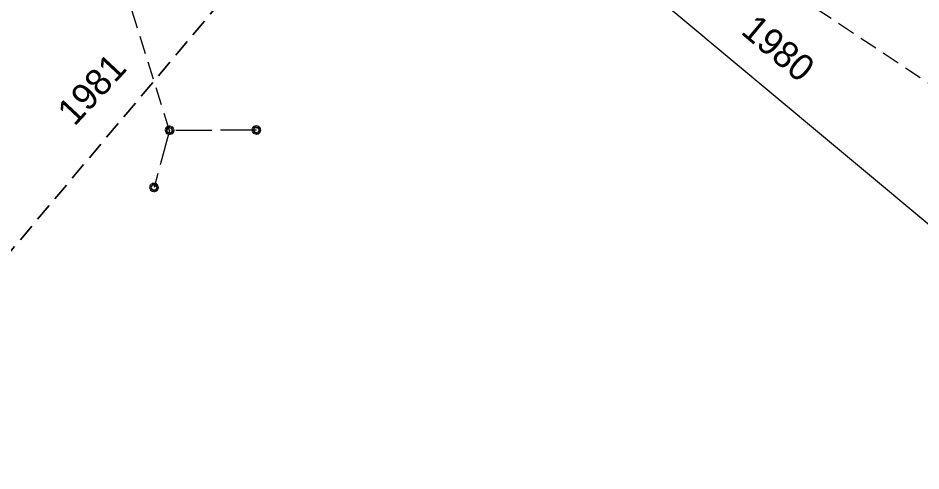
# Model space of a CAD drawing. Extents: x -742876 to -742577, y -1054710 to -1054452.
# Drawn here: x -742762.7 to -742708.1, y -1054549.5 to -1054522.1 of the extents above; entities that cross this region are included whole.
import ezdxf

# ---------------------------------------------------------------- set-up
doc = ezdxf.new("R2010")
doc.units = 0
doc.header["$LTSCALE"] = 0.36
doc.linetypes.add('LONG_DASHED', pattern=[7.5, 6, -1.5])
doc.linetypes.add('MEDIUM_DASHED', pattern=[4.5, 3, -1.5])
for name, color, linetype, lineweight in [('1', 7, 'MEDIUM_DASHED', 25), ('4', 7, 'Continuous', 13), ('8', 7, 'Continuous', 13)]:
    doc.layers.add(name, color=color, linetype=linetype, lineweight=lineweight)

msp = doc.modelspace()

# ---------------------------------------------------------------- linework, layer by layer
at = {"layer": '4', "linetype": 'MEDIUM_DASHED', "lineweight": 25}
msp.add_lwpolyline([(-742753.489, -1054528.94), (-742756.25, -1054520.12), (-742754.84, -1054517.31), (-742755.66, -1054516.33), (-742766.1, -1054507.8), (-742772.293, -1054515.246), (-742785.96, -1054502.911)], dxfattribs=at)
at = {"layer": '4'}
for points in [[(-742753.225, -1054528.927), (-742753.23, -1054528.871), (-742753.247, -1054528.818), (-742753.276, -1054528.769), (-742753.315, -1054528.728), (-742753.36, -1054528.696), (-742753.413, -1054528.674), (-742753.468, -1054528.663), (-742753.524, -1054528.665), (-742753.578, -1054528.678), (-742753.629, -1054528.703), (-742753.674, -1054528.738), (-742753.71, -1054528.781), (-742753.735, -1054528.831), (-742753.75, -1054528.886), (-742753.752, -1054528.942), (-742753.744, -1054528.997), (-742753.723, -1054529.05), (-742753.691, -1054529.096), (-742753.651, -1054529.135), (-742753.603, -1054529.165), (-742753.551, -1054529.184), (-742753.495, -1054529.191), (-742753.438, -1054529.187), (-742753.384, -1054529.17), (-742753.335, -1054529.143), (-742753.294, -1054529.105), (-742753.261, -1054529.06), (-742753.237, -1054529.009), (-742753.225, -1054528.954)], [(-742753.284, -1054528.93), (-742753.289, -1054528.881), (-742753.308, -1054528.835), (-742753.335, -1054528.794), (-742753.372, -1054528.761), (-742753.416, -1054528.739), (-742753.465, -1054528.727), (-742753.514, -1054528.727), (-742753.561, -1054528.739), (-742753.605, -1054528.762), (-742753.642, -1054528.795), (-742753.671, -1054528.836), (-742753.688, -1054528.883), (-742753.693, -1054528.932), (-742753.686, -1054528.981), (-742753.669, -1054529.027), (-742753.641, -1054529.067), (-742753.603, -1054529.1), (-742753.559, -1054529.122), (-742753.511, -1054529.134), (-742753.462, -1054529.133), (-742753.414, -1054529.121), (-742753.37, -1054529.097), (-742753.333, -1054529.064), (-742753.306, -1054529.023), (-742753.289, -1054528.976)], [(-742747.981, -1054528.913), (-742747.987, -1054528.857), (-742748.004, -1054528.804), (-742748.032, -1054528.755), (-742748.071, -1054528.714), (-742748.117, -1054528.682), (-742748.169, -1054528.66), (-742748.224, -1054528.649), (-742748.28, -1054528.651), (-742748.335, -1054528.664), (-742748.386, -1054528.689), (-742748.43, -1054528.724), (-742748.466, -1054528.767), (-742748.491, -1054528.817), (-742748.506, -1054528.872), (-742748.509, -1054528.928), (-742748.5, -1054528.983), (-742748.479, -1054529.036), (-742748.448, -1054529.082), (-742748.407, -1054529.121), (-742748.36, -1054529.151), (-742748.307, -1054529.17), (-742748.251, -1054529.177), (-742748.195, -1054529.173), (-742748.141, -1054529.156), (-742748.092, -1054529.129), (-742748.05, -1054529.091), (-742748.017, -1054529.046), (-742747.994, -1054528.995), (-742747.982, -1054528.94)], [(-742748.04, -1054528.916), (-742748.046, -1054528.867), (-742748.064, -1054528.821), (-742748.092, -1054528.78), (-742748.129, -1054528.747), (-742748.173, -1054528.725), (-742748.221, -1054528.713), (-742748.27, -1054528.713), (-742748.318, -1054528.725), (-742748.362, -1054528.748), (-742748.399, -1054528.781), (-742748.427, -1054528.822), (-742748.444, -1054528.869), (-742748.45, -1054528.918), (-742748.443, -1054528.967), (-742748.425, -1054529.013), (-742748.397, -1054529.053), (-742748.36, -1054529.086), (-742748.316, -1054529.108), (-742748.267, -1054529.12), (-742748.218, -1054529.119), (-742748.17, -1054529.107), (-742748.127, -1054529.083), (-742748.09, -1054529.05), (-742748.062, -1054529.009), (-742748.046, -1054528.962)], [(-742753.343, -1054528.934), (-742753.348, -1054528.892), (-742753.365, -1054528.854), (-742753.394, -1054528.823), (-742753.428, -1054528.8), (-742753.468, -1054528.789), (-742753.511, -1054528.789), (-742753.551, -1054528.801), (-742753.585, -1054528.824), (-742753.612, -1054528.856), (-742753.629, -1054528.894), (-742753.634, -1054528.935), (-742753.629, -1054528.977), (-742753.61, -1054529.014), (-742753.583, -1054529.046), (-742753.546, -1054529.068), (-742753.507, -1054529.079), (-742753.465, -1054529.078), (-742753.424, -1054529.065), (-742753.391, -1054529.042), (-742753.364, -1054529.009), (-742753.348, -1054528.971)], [(-742748.099, -1054528.92), (-742748.105, -1054528.878), (-742748.122, -1054528.84), (-742748.15, -1054528.809), (-742748.184, -1054528.786), (-742748.225, -1054528.775), (-742748.267, -1054528.775), (-742748.307, -1054528.787), (-742748.342, -1054528.81), (-742748.369, -1054528.842), (-742748.386, -1054528.88), (-742748.391, -1054528.921), (-742748.385, -1054528.963), (-742748.367, -1054529), (-742748.339, -1054529.032), (-742748.303, -1054529.054), (-742748.263, -1054529.065), (-742748.221, -1054529.064), (-742748.181, -1054529.051), (-742748.147, -1054529.028), (-742748.12, -1054528.995), (-742748.104, -1054528.957)], [(-742754.17, -1054532.381), (-742754.176, -1054532.325), (-742754.193, -1054532.272), (-742754.222, -1054532.223), (-742754.26, -1054532.182), (-742754.306, -1054532.15), (-742754.358, -1054532.128), (-742754.413, -1054532.117), (-742754.469, -1054532.119), (-742754.524, -1054532.132), (-742754.575, -1054532.157), (-742754.619, -1054532.192), (-742754.655, -1054532.235), (-742754.68, -1054532.285), (-742754.695, -1054532.34), (-742754.698, -1054532.396), (-742754.689, -1054532.451), (-742754.668, -1054532.504), (-742754.637, -1054532.55), (-742754.597, -1054532.589), (-742754.549, -1054532.619), (-742754.496, -1054532.638), (-742754.44, -1054532.645), (-742754.384, -1054532.641), (-742754.33, -1054532.624), (-742754.281, -1054532.597), (-742754.239, -1054532.559), (-742754.206, -1054532.514), (-742754.183, -1054532.463), (-742754.171, -1054532.408)], [(-742754.229, -1054532.384), (-742754.235, -1054532.335), (-742754.253, -1054532.289), (-742754.281, -1054532.248), (-742754.318, -1054532.215), (-742754.362, -1054532.193), (-742754.41, -1054532.181), (-742754.459, -1054532.181), (-742754.507, -1054532.193), (-742754.551, -1054532.216), (-742754.588, -1054532.249), (-742754.616, -1054532.29), (-742754.633, -1054532.337), (-742754.639, -1054532.386), (-742754.632, -1054532.435), (-742754.614, -1054532.481), (-742754.586, -1054532.521), (-742754.549, -1054532.554), (-742754.505, -1054532.576), (-742754.456, -1054532.588), (-742754.407, -1054532.587), (-742754.359, -1054532.575), (-742754.316, -1054532.551), (-742754.279, -1054532.518), (-742754.251, -1054532.477), (-742754.235, -1054532.43)], [(-742754.288, -1054532.388), (-742754.294, -1054532.346), (-742754.311, -1054532.308), (-742754.339, -1054532.277), (-742754.374, -1054532.254), (-742754.414, -1054532.243), (-742754.456, -1054532.243), (-742754.496, -1054532.255), (-742754.531, -1054532.278), (-742754.558, -1054532.31), (-742754.575, -1054532.348), (-742754.58, -1054532.389), (-742754.574, -1054532.431), (-742754.556, -1054532.468), (-742754.528, -1054532.5), (-742754.492, -1054532.522), (-742754.452, -1054532.533), (-742754.41, -1054532.532), (-742754.37, -1054532.519), (-742754.336, -1054532.496), (-742754.309, -1054532.463), (-742754.293, -1054532.425)]]:
    msp.add_lwpolyline(points, close=True, dxfattribs=at)
at = {"layer": '4', "linetype": 'LONG_DASHED', "lineweight": 25}
msp.add_lwpolyline([(-742748.245, -1054528.926), (-742753.489, -1054528.94), (-742754.434, -1054532.394)], dxfattribs=at)
at = {"layer": '8', "linetype": 'MEDIUM_DASHED', "lineweight": 25}
msp.add_line((-742735.984, -1054507.208), (-742682.223, -1054542.964), dxfattribs=at)
at = {"layer": '8', "lineweight": 25}
msp.add_line((-742737.719, -1054509.488), (-742691.8, -1054547.79), dxfattribs=at)
at = {"layer": '8', "linetype": 'MEDIUM_DASHED', "lineweight": 35}
msp.add_lwpolyline([(-742829.868, -1054622.418), (-742815.739, -1054598.74), (-742738.263, -1054506.754)], dxfattribs=at)
msp.add_lwpolyline([(-742829.868, -1054622.418), (-742815.739, -1054598.74), (-742738.263, -1054506.754)], dxfattribs=at)

# ---------------------------------------------------------------- texts
at = {"layer": '1'}
for s, rotation, p in [('1980', 320, (-742719.023, -1054523.046)), ('1981', 47, (-742759.244, -1054528.729))]:
    msp.add_text(s, height=1.6, rotation=rotation, dxfattribs=at).set_placement(p)

doc.saveas('drawing.dxf')
